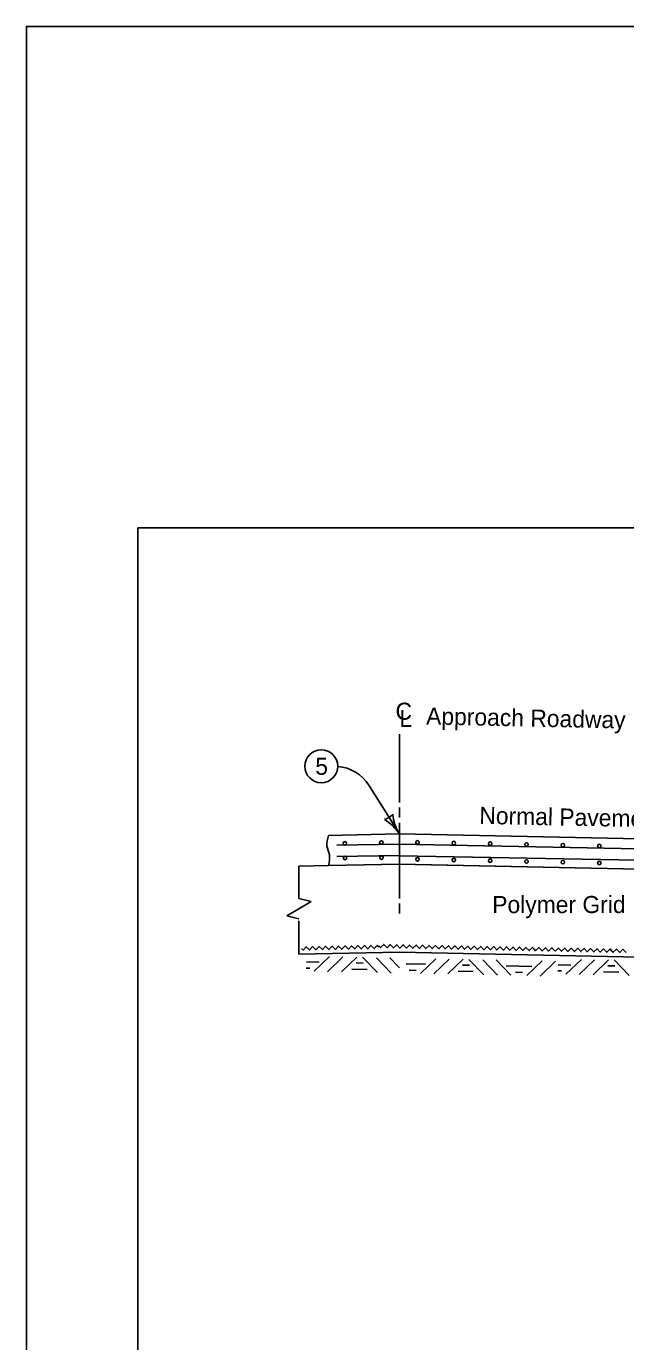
# Model space of a CAD drawing. Extents: x -2135039 to -2124495, y -2139046 to -2132546.
# Drawn here: x -2127839 to -2127278, y -2133778 to -2132546 of the extents above; entities that cross this region are included whole.
import ezdxf

# ---------------------------------------------------------------- set-up
doc = ezdxf.new("R2010")
doc.units = 0
for name, color, linetype in [('BridgeSuperStructureExisting', 7, 'Continuous'), ('dsnAlignmentStation', 7, 'Continuous'), ('dsnStdLabel', 7, 'Continuous'), ('dsnStdLineWork', 7, 'Continuous')]:
    doc.layers.add(name, color=color, linetype=linetype)

msp = doc.modelspace()

# ---------------------------------------------------------------- linework, layer by layer
at = {"layer": 'BridgeSuperStructureExisting'}
for p, q in [((-2127518.3, -2133256.8), (-2127489.7, -2133302.3)), ((-2127489.7, -2133302.3), (-2127556.1, -2133303.7)), ((-2127489.7, -2133302.3), (-2127556.1, -2133303.7)), ((-2126779.5, -2133316.6), (-2127489.7, -2133302.3)), ((-2127489.7, -2133302.3), (-2126779.5, -2133316.6)), ((-2127489.8, -2133311.8), (-2127548.3, -2133313)), ((-2127489.8, -2133311.8), (-2126758.1, -2133326.5)), ((-2127556.1, -2133332), (-2127490.3, -2133330.7)), ((-2127489.2, -2133330.7), (-2127556.1, -2133332)), ((-2127489.8, -2133322.6), (-2127548.3, -2133323.3)), ((-2127490.3, -2133330.7), (-2127489.7, -2133330.7)), ((-2127490.3, -2133330.7), (-2126741.2, -2133345.7)), ((-2127489.7, -2133330.7), (-2127489.2, -2133330.7)), ((-2127489.2, -2133330.7), (-2126741.2, -2133345.7)), ((-2127473, -2133324.4), (-2127473, -2133324.4)), ((-2127438.9, -2133325.1), (-2127438.9, -2133325.1)), ((-2127404.9, -2133325.8), (-2127404.9, -2133325.8)), ((-2127370.9, -2133326.5), (-2127370.9, -2133326.5)), ((-2127302.8, -2133327.8), (-2127302.8, -2133327.8)), ((-2127556.1, -2133332), (-2127583.7, -2133332.6)), ((-2127583.7, -2133332.6), (-2127583.7, -2133362.8)), ((-2127583.7, -2133362.8), (-2127572.3, -2133365.7)), ((-2127572.3, -2133365.7), (-2127583.7, -2133372.3)), ((-2127583.7, -2133372.3), (-2127595, -2133378.9)), ((-2127595, -2133378.9), (-2127583.7, -2133381.7)), ((-2127583.7, -2133383.7), (-2127583.7, -2133415)), ((-2127489.7, -2133413.1), (-2127583.7, -2133415)), ((-2127555, -2133417.1), (-2127569.5, -2133430.9)), ((-2127489.7, -2133413.1), (-2126673.1, -2133429.5)), ((-2127542.6, -2133417.5), (-2127557, -2133431.4)), ((-2127529.6, -2133417.6), (-2127544, -2133431.4)), ((-2127524.2, -2133417.7), (-2127510.3, -2133432.1)), ((-2127511.2, -2133418.2), (-2127497.3, -2133432.6)), ((-2127498.7, -2133418.2), (-2127489.6, -2133427.7)), ((-2127455.5, -2133419.1), (-2127469.9, -2133432.9)), ((-2127443.1, -2133419.5), (-2127457.5, -2133433.4)), ((-2127430.1, -2133419.6), (-2127444.5, -2133433.4)), ((-2127424.6, -2133419.7), (-2127410.8, -2133434.1)), ((-2127411.6, -2133420.2), (-2127397.8, -2133434.6)), ((-2127399.2, -2133420.2), (-2127385.3, -2133434.6)), ((-2127356, -2133421.1), (-2127370.4, -2133434.9)), ((-2127343.5, -2133421.5), (-2127358, -2133435.4)), ((-2127319.4, -2133419.7), (-2127333.9, -2133433.5)), ((-2127307, -2133420.2), (-2127321.4, -2133434)), ((-2127294, -2133420.2), (-2127308.4, -2133434.1)), ((-2127288.6, -2133420.3), (-2127274.7, -2133434.7))]:
    msp.add_line(p, q, dxfattribs=at)
for points in [[(-2127489.7, -2133208.9), (-2127489.7, -2133272.9)], [(-2127489.7, -2133277.6), (-2127489.7, -2133287)], [(-2127489.7, -2133291.8), (-2127489.7, -2133362.7)], [(-2127490.3, -2133330.7), (-2127490.3, -2133330.7)], [(-2127489.2, -2133330.7), (-2127489.2, -2133330.7)], [(-2127489.7, -2133367.4), (-2127489.7, -2133376.8)], [(-2127581.4, -2133409.5), (-2127579.9, -2133411), (-2127576.9, -2133407.9), (-2127573.8, -2133410.9), (-2127570.9, -2133407.8), (-2127567.8, -2133410.8), (-2127564.8, -2133407.7), (-2127561.7, -2133410.6), (-2127558.8, -2133407.5), (-2127555.7, -2133410.5), (-2127552.7, -2133407.4), (-2127549.6, -2133410.4), (-2127546.7, -2133407.3), (-2127543.6, -2133410.3), (-2127540.6, -2133407.2), (-2127537.5, -2133410.1), (-2127534.6, -2133407.1), (-2127531.5, -2133410), (-2127528.5, -2133406.9), (-2127525.4, -2133409.9), (-2127522.5, -2133406.8), (-2127519.4, -2133409.8), (-2127516.4, -2133406.7), (-2127513.3, -2133409.7), (-2127510.4, -2133406.6), (-2127508.8, -2133408.1)], [(-2127508.8, -2133407.2), (-2127507.3, -2133408.7), (-2127504.3, -2133405.8), (-2127501.3, -2133408.9), (-2127498.2, -2133405.9), (-2127495.2, -2133409), (-2127492.2, -2133406), (-2127489.2, -2133409.1), (-2127486.1, -2133406.1), (-2127483.1, -2133409.2), (-2127480.1, -2133406.3), (-2127477.1, -2133409.4), (-2127474, -2133406.4), (-2127471, -2133409.5), (-2127468, -2133406.5), (-2127465, -2133409.6), (-2127461.9, -2133406.6), (-2127458.9, -2133409.7), (-2127455.9, -2133406.8), (-2127452.9, -2133409.8), (-2127449.8, -2133406.9), (-2127446.9, -2133410), (-2127443.8, -2133407), (-2127440.8, -2133410.1), (-2127437.7, -2133407.1), (-2127436.2, -2133408.7)], [(-2127436.2, -2133408.7), (-2127434.8, -2133410.2), (-2127431.7, -2133407.2), (-2127428.7, -2133410.3), (-2127425.6, -2133407.4), (-2127422.7, -2133410.4), (-2127419.6, -2133407.5), (-2127416.6, -2133410.6), (-2127413.5, -2133407.6), (-2127410.6, -2133410.7), (-2127407.5, -2133407.7), (-2127404.5, -2133410.8), (-2127401.4, -2133407.8), (-2127398.5, -2133410.9), (-2127395.4, -2133408), (-2127392.4, -2133411), (-2127389.3, -2133408.1), (-2127386.4, -2133411.2), (-2127383.3, -2133408.2), (-2127380.3, -2133411.3), (-2127377.2, -2133408.3), (-2127374.3, -2133411.4), (-2127371.2, -2133408.5), (-2127368.2, -2133411.5), (-2127365.1, -2133408.6), (-2127363.7, -2133410.1)], [(-2127363.7, -2133410.1), (-2127362.2, -2133411.7), (-2127359.1, -2133408.7), (-2127356.1, -2133411.8), (-2127353, -2133408.8), (-2127350.1, -2133411.9), (-2127347, -2133408.9), (-2127344, -2133412), (-2127340.9, -2133409.1), (-2127338, -2133412.1), (-2127334.9, -2133409.2), (-2127331.9, -2133412.3), (-2127328.8, -2133409.3), (-2127325.9, -2133412.4), (-2127322.8, -2133409.4), (-2127319.8, -2133412.5), (-2127316.7, -2133409.5), (-2127313.8, -2133412.6), (-2127310.7, -2133409.7), (-2127307.7, -2133412.7), (-2127304.6, -2133409.8), (-2127301.7, -2133412.9), (-2127298.6, -2133409.9), (-2127295.6, -2133413), (-2127292.5, -2133410), (-2127291.1, -2133411.6)], [(-2127291.1, -2133411.6), (-2127289.6, -2133413.1), (-2127286.5, -2133410.1), (-2127283.5, -2133413.2), (-2127280.5, -2133410.3), (-2127277.5, -2133413.4)], [(-2127576.9, -2133427.9), (-2127573.6, -2133428)], [(-2127576.8, -2133422.1), (-2127564.7, -2133422.3)], [(-2127534.2, -2133428.8), (-2127520, -2133429.1)], [(-2127530.3, -2133423.1), (-2127523.7, -2133423.2)], [(-2127483.3, -2133424), (-2127465.2, -2133424.3)], [(-2127430.7, -2133425.1), (-2127424.2, -2133425.2)], [(-2127389.7, -2133425.9), (-2127365.7, -2133426.3)], [(-2127341.2, -2133424.7), (-2127329.1, -2133425)], [(-2127294.7, -2133425.7), (-2127288.1, -2133425.8)], [(-2127480.6, -2133429.8), (-2127474.1, -2133430)], [(-2127434.7, -2133430.8), (-2127420.5, -2133431.1)], [(-2127381.1, -2133431.8), (-2127374.5, -2133432)], [(-2127341.3, -2133430.5), (-2127338, -2133430.6)], [(-2127298.6, -2133431.5), (-2127284.4, -2133431.8)]]:
    msp.add_lwpolyline(points, dxfattribs=at)
for centre, radius in [((-2127562.8, -2133239), 15.4), ((-2127540.8, -2133311.1), 1.65), ((-2127506.6, -2133310.4), 1.65), ((-2127472.8, -2133310.2), 1.65), ((-2127438.8, -2133310.9), 1.65), ((-2127404.7, -2133311.5), 1.65), ((-2127370.7, -2133312.2), 1.65), ((-2127336.7, -2133312.9), 1.65), ((-2127302.6, -2133313.6), 1.65), ((-2127540.6, -2133324.8), 1.65), ((-2127506.5, -2133324.5), 1.65), ((-2127472.8, -2133326.1), 1.65), ((-2127438.8, -2133326.7), 1.65), ((-2127404.7, -2133327.4), 1.65), ((-2127370.7, -2133328.1), 1.65), ((-2127336.7, -2133328.8), 1.65), ((-2127302.6, -2133329.5), 1.65)]:
    msp.add_circle(centre, radius, dxfattribs=at)
for centre, radius, start, end in [((-2127550.3, -2133276.9), 37.8, 32.09, 85.5904), ((-2127507.6, -2133273.8), 15.5, 284.3569, 319.8236), ((-2127507.6, -2133273.8), 15.5, 284.3569, 319.8236), ((-2127523.8, -2133323.7), 40.2, 32.0903, 60.1628), ((-2127523.8, -2133323.7), 40.2, 32.0903, 60.1628), ((-2127455.7, -2133281), 40.2, 184.0178, 212.0903), ((-2127455.7, -2133281), 40.2, 184.0178, 212.0903)]:
    msp.add_arc(centre, radius, start, end, dxfattribs=at)
msp.add_spline([(-2127556.1, -2133303.7), (-2127557.6, -2133313.7), (-2127555.2, -2133321.9), (-2127556.1, -2133332)], degree=3, dxfattribs=at)
msp.add_spline([(-2127556.1, -2133303.7), (-2127557.6, -2133313.7), (-2127555.2, -2133321.9), (-2127556.1, -2133332)], degree=3, dxfattribs=at)
at = {"layer": 'dsnAlignmentStation'}
msp.add_lwpolyline([(-2127734.4, -2133016), (-2124599.4, -2133016), (-2124599.4, -2135026), (-2127734.4, -2135026)], close=True, dxfattribs=at)
at = {"layer": 'dsnStdLabel'}
msp.add_line((-2126758.2, -2133336.4), (-2127489.8, -2133322.9), dxfattribs=at)
at = {"layer": 'dsnStdLineWork'}
msp.add_lwpolyline([(-2127838.9, -2135130.5), (-2124494.9, -2135130.5), (-2124494.9, -2132546.5), (-2127838.9, -2132546.5)], close=True, dxfattribs=at)

# ---------------------------------------------------------------- texts
at = {"layer": 'dsnStdLabel'}
for s, p in [('C', (-2127493.3, -2133195.5)), ('L', (-2127489.7, -2133202.2)), ('5', (-2127568.4, -2133247)), ('Polymer Grid', (-2127402.8, -2133376.4))]:
    msp.add_text(s, height=16, dxfattribs=at).set_placement(p)
for s, p in [('Approach Roadway', (-2127464.8, -2133199.9)), ('Normal Pavement Slope', (-2127415, -2133292.9))]:
    msp.add_text(s, height=16, rotation=358.8502, dxfattribs=at).set_placement(p)

doc.saveas('drawing.dxf')
